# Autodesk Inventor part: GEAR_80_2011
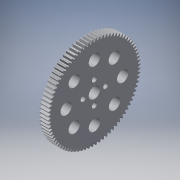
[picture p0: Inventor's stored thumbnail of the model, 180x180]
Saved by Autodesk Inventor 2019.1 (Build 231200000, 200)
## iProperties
Created: 2011-09
Part Number: GEAR_80_2011
Document SubType Name: Modeling
Designer: jagalloro
Density: 2.71 g/cm^3
Material: Aluminum 6061
Mass: 45.3714 g
Surface Area: 95.7236 cm^2
Volume: 16.7422 cm^3
Appearance: Aluminum - Flat
Translation Standard: STEP AP203
FileName: GEAR_80_2011
PreProcessor: PRO/ENGINEER BY PARAMETRIC TECHNOLOGY CORPORATION, 2010480
PostProcessor: Build: 239, Release: 2011 RTM - Date: Wed 02/17/2010
Sent Units: millimeter
Uncertainty: 0.009293057730057
Author: jagalloro
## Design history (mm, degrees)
feature "Base1"
node "GEAR_80_2011"
other parameters: "d0" = 0, "d1" = 0
